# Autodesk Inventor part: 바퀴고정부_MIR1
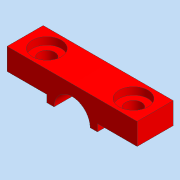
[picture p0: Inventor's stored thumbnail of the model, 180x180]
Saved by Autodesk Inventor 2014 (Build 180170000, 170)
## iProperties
Created: 2015-05
Part Number: 바퀴고정부_MIR1
Material: 일반
Vendor: CBT Solutions
Document SubType Name: 모델링
Designer: Administrator
Appearance: 기본값
Company: 한국ATC센터
Author: KYOUNG IL JANG
Comments: 파생
d0: 1.000 ul
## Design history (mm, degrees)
derived "바퀴고정부.ipt" dims count "d0" = 1
feature "솔리드1::바퀴고정부.ipt" dims count "d0" = 1
tag "피쳐 태그1"
node "솔리드1"
